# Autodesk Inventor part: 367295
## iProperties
Created: 2006-06
Part Number: 367295
Document SubType Name: Modeling
Designer: I.Baliuc
Material: 8.8 vz
Description: Sperrzahnschraube
Density: 7.85 g/cm^3
Mass: 28.7654 g
Surface Area: 17.1253 cm^2
Volume: 3.66438 cm^3
Abmessung: M10 x 20
Author: T.Messerschmitt
Revision Number: 367295
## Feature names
1. Basis1
